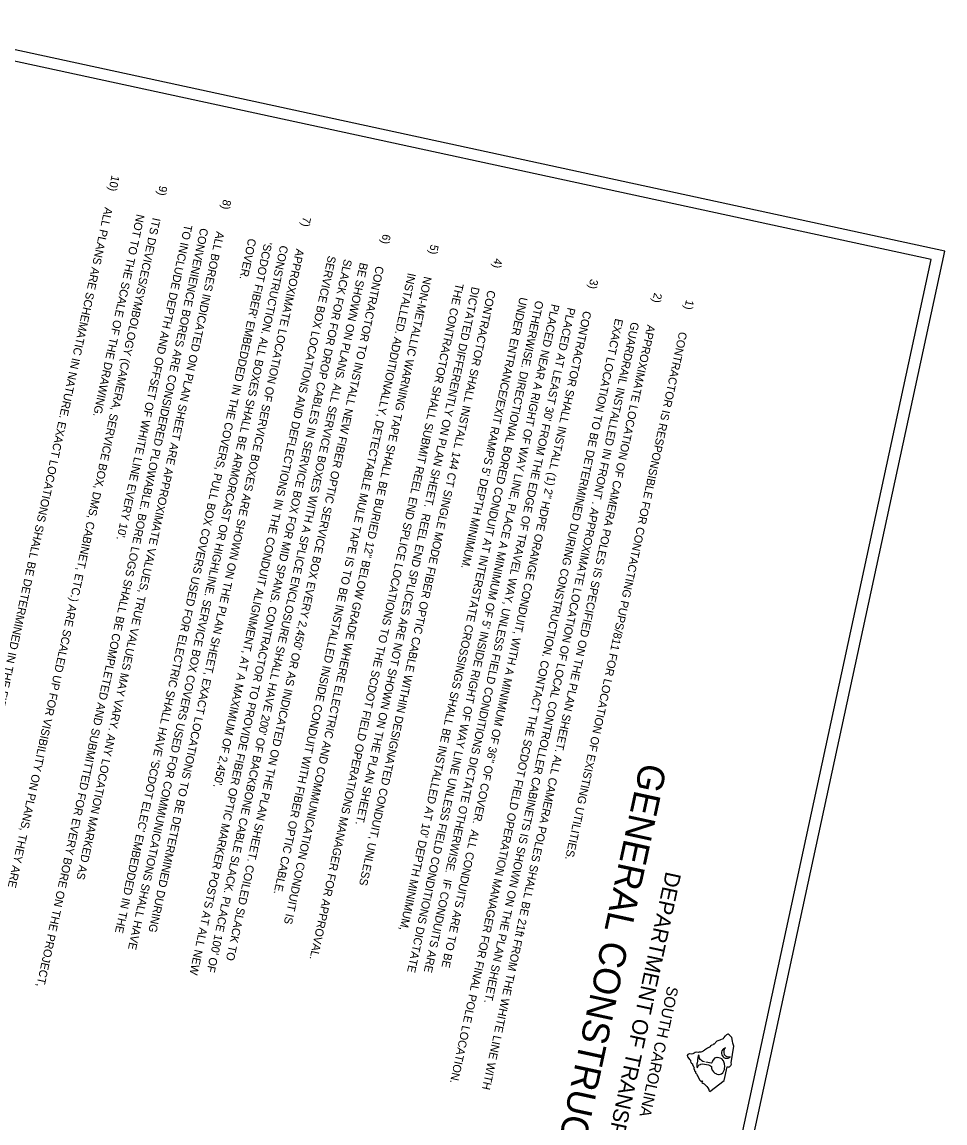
# Model space of a CAD drawing. Extents: x 1897817 to 2050613, y 442539 to 798440.
# Drawn here: x 1977576 to 1979013, y 783329 to 785042 of the extents above; entities that cross this region are included whole.
import ezdxf

# ---------------------------------------------------------------- set-up
doc = ezdxf.new("R2010")
doc.units = 0
for name, color, linetype in [('Default', 7, 'Continuous'), ('RD_SHT_Bndy', 7, 'Continuous'), ('RD_SHT_IplotShp', 7, 'Continuous')]:
    doc.layers.add(name, color=color, linetype=linetype)

msp = doc.modelspace()

# ---------------------------------------------------------------- linework, layer by layer
at = {"layer": 'Default'}
for p, q in [((1978668.6, 783462), (1978667.4, 783459.9)), ((1978671, 783445.8), (1978671, 783445.8)), ((1978633, 783426.7), (1978631.8, 783427.6)), ((1978634.1, 783425.9), (1978633, 783426.7)), ((1978635.6, 783424.9), (1978634.1, 783425.9)), ((1978638.3, 783424.2), (1978635.6, 783424.9)), ((1978649, 783421.9), (1978640.2, 783423.8)), ((1978647.7, 783418.1), (1978649.2, 783416.7)), ((1978669.5, 783413.7), (1978669.5, 783413.7)), ((1978646.5, 783378.1), (1978668.9, 783394.9))]:
    msp.add_line(p, q, dxfattribs=at)
for points in [[(1978667.4, 783459.9), (1978665.6, 783459.2), (1978663, 783458.6), (1978662.1, 783458), (1978657.6, 783456.3), (1978655.4, 783454), (1978654.7, 783453), (1978653.1, 783451.6), (1978652.4, 783451.5), (1978652, 783450.7), (1978649.9, 783450.2), (1978647.9, 783449.1), (1978646.9, 783447.5), (1978646.1, 783446.9), (1978642.8, 783445.4), (1978641.4, 783444.3), (1978638.3, 783442.4), (1978637.7, 783441.8), (1978636.4, 783441.4), (1978635.9, 783440.3), (1978632.8, 783439.2), (1978630.5, 783439.3), (1978629.8, 783439), (1978628.9, 783438.8), (1978625.5, 783439.1), (1978624, 783438.8), (1978622, 783437.4), (1978620.2, 783436.8), (1978617.6, 783436.3), (1978615.7, 783436.4), (1978614.9, 783436.8), (1978613.3, 783436.3), (1978612.6, 783435.8), (1978611.5, 783433.9), (1978611.9, 783432.1), (1978613.8, 783429.1), (1978615.1, 783427.8), (1978616.1, 783427.6), (1978616.7, 783426.8), (1978616.5, 783425), (1978617.3, 783423.2), (1978618.1, 783422.2), (1978619.4, 783420.9), (1978619.5, 783419.9), (1978620.5, 783417.4), (1978621.9, 783416.4), (1978622.1, 783415.5), (1978621.9, 783414.6), (1978621.8, 783413.6), (1978622.7, 783411.3), (1978622.8, 783410.3), (1978624.2, 783409.3), (1978624.5, 783408.2), (1978624.2, 783407.6), (1978624.3, 783406.8), (1978626.4, 783404.8), (1978626.9, 783402.7), (1978628.5, 783400.9), (1978628.9, 783399), (1978631.2, 783395.5), (1978632.7, 783394.2), (1978633.5, 783394.2), (1978634.3, 783394.5), (1978635, 783394), (1978634.4, 783392.2), (1978635.8, 783390.9), (1978637.6, 783390), (1978642.2, 783386), (1978643.7, 783383.9), (1978644.8, 783381.2)], [(1978673.4, 783416.3), (1978674.3, 783416.5), (1978675.2, 783416.1), (1978676, 783416.3), (1978677, 783416.4), (1978679.1, 783418.4), (1978680.1, 783420.7), (1978679.8, 783422.4), (1978684.1, 783448.4), (1978683.2, 783450.1), (1978682.5, 783453.1), (1978681.7, 783456.2), (1978681.1, 783461.8), (1978676.9, 783466.2), (1978675.3, 783467.2), (1978674.5, 783467.4), (1978672.4, 783466.2), (1978670.8, 783464.7), (1978669.9, 783464.2), (1978668.6, 783462)], [(1978631.8, 783427.6), (1978630.4, 783429.3), (1978629.8, 783432.9), (1978630, 783433.8), (1978629.1, 783434.3), (1978628.1, 783431.1), (1978627.7, 783430.2), (1978627.2, 783427.7), (1978627.3, 783425.8), (1978626.8, 783422.3), (1978626.5, 783421.5), (1978626.5, 783417), (1978626.8, 783415), (1978627.7, 783416.5), (1978628.4, 783418.1), (1978629.9, 783419.3)], [(1978650.2, 783423.6), (1978649.8, 783422.8), (1978649, 783422)], [(1978657.6, 783430.5), (1978656.8, 783430.7), (1978653.9, 783429.6), (1978651.8, 783426.8), (1978651, 783426.1), (1978651, 783425.2), (1978650.2, 783423.6)], [(1978665.9, 783428.1), (1978665.3, 783428.7), (1978662.8, 783430), (1978658.6, 783430.8), (1978657.6, 783430.5)], [(1978667.7, 783425.6), (1978667.5, 783426.4), (1978665.9, 783428.1)], [(1978669.5, 783413.7), (1978670, 783416.9), (1978669.6, 783421.1), (1978667.7, 783425.6)], [(1978629.9, 783419.3), (1978632, 783420.2)], [(1978632, 783420.2), (1978632.6, 783420.4), (1978635.9, 783420.8)], [(1978635.9, 783420.8), (1978638.5, 783420.6)], [(1978638.5, 783420.6), (1978644.4, 783419.3), (1978647.7, 783418.1)], [(1978649.2, 783416.7), (1978649.3, 783414.9), (1978649.4, 783414.4), (1978649.4, 783414.4), (1978650.3, 783411.2), (1978650.6, 783410.7), (1978652.1, 783408.4), (1978653.3, 783407.5), (1978654.3, 783406.7), (1978656.1, 783405.9), (1978657.1, 783405.5)], [(1978661, 783404.5), (1978663.3, 783404.8), (1978665, 783405.6), (1978666.6, 783406.9), (1978667.5, 783408.3), (1978667.8, 783409)], [(1978667.8, 783409), (1978669.2, 783412.3), (1978669.5, 783413.7)], [(1978668.9, 783394.9), (1978668.9, 783395), (1978673.4, 783416.3)], [(1978657.1, 783405.5), (1978657.7, 783405), (1978660.2, 783404.5), (1978661, 783404.5)], [(1978644.8, 783381.2), (1978645, 783380.1), (1978645.8, 783379), (1978646.5, 783378.1)]]:
    msp.add_lwpolyline(points, dxfattribs=at)
for centre, major_axis, start_param, end_param in [((1978672.9, 783437.9), (-7.97, 1.72), 5.80475, 6.314402), ((1978672.9, 783437.9), (-7.97, 1.72), 5.447207, 5.79938), ((1978676.1, 783439.7), (-7.82, 1.69), 5.62785, 8.38372), ((1978672.9, 783437.9), (-7.97, 1.72), 5.160801, 5.435937), ((1978672.9, 783437.9), (-7.97, 1.72), 0.031979, 0.55843), ((1978672.9, 783437.9), (-7.97, 1.72), 0.563702, 0.788107), ((1978672.9, 783437.9), (-7.97, 1.72), 0.803027, 1.195383), ((1978672.9, 783437.9), (-7.97, 1.72), 1.204989, 1.500149), ((1978672.9, 783437.9), (-7.97, 1.72), 1.504214, 1.84923), ((1978672.9, 783437.9), (-7.97, 1.72), 1.863481, 2.248857), ((1978672.9, 783437.9), (-7.97, 1.72), 2.259865, 2.562019)]:
    msp.add_ellipse(centre, major_axis=major_axis, ratio=0.999097, start_param=start_param, end_param=end_param, dxfattribs=at)
at = {"layer": 'RD_SHT_Bndy'}
for p, q in [((1978991.1, 784672.1), (1977385.5, 785019.6)), ((1978448.1, 782163.8), (1978991.1, 784672.1))]:
    msp.add_line(p, q, dxfattribs=at)
at = {"layer": 'RD_SHT_IplotShp'}
msp.add_lwpolyline([(1977366.1, 785041.7), (1976813.4, 782488), (1978459.8, 782131.6), (1979012.6, 784685.3)], close=True, dxfattribs=at)

# ---------------------------------------------------------------- texts
at = {"layer": 'Default'}
for s, height, p in [('10)', 12.71, (1977715.7, 784803.9)), ('9)  ', 12.71, (1977790.2, 784787.8)), ('8)', 12.71, (1977889.5, 784766.3)), ('ALL PLANS ARE SCHEMATIC IN NATURE. EXACT LOCATIONS SHALL BE DETERMINED IN THE FIELD.', 12.706, (1977704.9, 784754.3)), ('NOT TO THE SCALE OF THE DRAWING.', 12.706, (1977754.6, 784743.5)), ('ITS DEVICES/SYMBOLOGY (CAMERA, SERVICE BOX, DMS, CABINET, ETC.) ARE SCALED UP FOR VISIBILITY ON PLANS, THEY ARE', 12.7057, (1977779.4, 784738.1)), ('7)', 12.71, (1978013.7, 784739.4)), ('CONVENIENCE BORES ARE CONSIDERED PLOWABLE. BORE LOGS SHALL BE COMPLETED AND SUBMITTED FOR EVERY BORE ON THE PROJECT, ', 12.7057, (1977853.9, 784722)), ('ALL BORES INDICATED ON PLAN SHEET ARE APPROXIMATE VALUES, TRUE VALUES MAY VARY. ANY LOCATION MARKED AS', 12.7057, (1977878.8, 784716.6)), ("TO INCLUDE DEPTH AND OFFSET OF WHITE LINE EVERY 10'.", 12.706, (1977829.1, 784727.4)), ('6)', 12.71, (1978137.9, 784712.5)), ("'SCDOT FIBER' EMBEDDED IN THE COVERS, PULL BOX COVERS USED FOR ELECTRIC SHALL HAVE 'SCDOT ELEC' EMBEDDED IN THE ", 12.7057, (1977953.3, 784700.5)), ('CONSTRUCTION. ALL BOXES SHALL BE ARMORCAST OR HIGHLINE. SERVICE BOX COVERS USED FOR COMMUNICATIONS SHALL HAVE ', 12.7057, (1977978.1, 784695.1)), ('COVER.', 12.71, (1977928.4, 784705.9)), ('5)', 12.71, (1978212.4, 784696.4)), ('APPROXIMATE LOCATION OF SERVICE BOXES ARE SHOWN ON THE PLAN SHEET, EXACT LOCATIONS TO BE DETERMINED DURING ', 12.7057, (1978002.9, 784689.7)), ("SERVICE BOX LOCATIONS AND DEFLECTIONS IN THE CONDUIT ALIGNMENT, AT A MAXIMUM OF 2,450'. ", 12.706, (1978052.6, 784679)), ('4)', 12.71, (1978311.7, 784674.9)), ('SLACK FOR FOR DROP CABLES IN SERVICE BOX FOR MID SPANS. CONTRACTOR TO PROVIDE FIBER OPTIC MARKER POSTS AT ALL NEW ', 12.7057, (1978077.5, 784673.6)), ("BE SHOWN ON PLANS. ALL SERVICE BOXES WITH A SPLICE ENCLOSURE SHALL HAVE 200' OF BACKBONE CABLE SLACK. PLACE 100' OF ", 12.7057, (1978102.3, 784668.2)), ("CONTRACTOR TO INSTALL NEW FIBER OPTIC SERVICE BOX EVERY 2,450' OR AS INDICATED ON THE PLAN SHEET. COILED SLACK TO ", 12.7057, (1978127.1, 784662.9)), ('INSTALLED. ADDITIONALLY, DETECTABLE MULE TAPE IS TO BE INSTALLED INSIDE CONDUIT WITH FIBER OPTIC CABLE.', 12.7057, (1978176.8, 784652.1)), ('NON-METALLIC WARNING TAPE SHALL BE BURIED 12" BELOW GRADE WHERE ELECTRIC AND COMMUNICATION CONDUIT IS ', 12.7057, (1978201.6, 784646.7)), ('3)', 12.71, (1978460.7, 784642.6)), ('THE CONTRACTOR SHALL SUBMIT REEL END SPLICE LOCATIONS TO THE SCDOT FIELD OPERATIONS MANAGER FOR APPROVAL.', 12.7057, (1978251.3, 784636)), ('DICTATED DIFFERENTLY ON PLAN SHEET.  REEL END SPLICES ARE NOT SHOWN ON THE PLAN SHEET. ', 12.706, (1978276.1, 784630.6)), ('CONTRACTOR SHALL INSTALL 144 CT SINGLE MODE FIBER OPTIC CABLE WITHIN DESIGNATED CONDUIT, UNLESS ', 12.706, (1978301, 784625.2)), ("OTHERWISE. DIRECTIONAL BORED CONDUIT AT INTERSTATE CROSSINGS SHALL BE INSTALLED AT 10' DEPTH MINIMUM, ", 12.7057, (1978375.5, 784609.1)), ("UNDER ENTRANCE/EXIT RAMPS 5' DEPTH MINIMUM.", 12.706, (1978350.7, 784614.5)), ('2)', 12.71, (1978560.1, 784621.1)), ('1)', 12.71, (1978609.8, 784610.4)), ("PLACED NEAR A RIGHT OF WAY LINE, PLACE A MINIMUM OF 5' INSIDE RIGHT OF WAY LINE UNLESS FIELD CONDITIONS DICTATE", 12.7057, (1978400.3, 784603.7)), ("PLACED AT LEAST 30' FROM THE EDGE OF TRAVEL WAY, UNLESS FIELD CONDITIONS DICTATE OTHERWISE.  IF CONDUITS ARE", 12.7057, (1978425.2, 784598.3)), ('CONTRACTOR SHALL INSTALL (1) 2" HDPE ORANGE CONDUIT, WITH A MINIMUM OF 36" OF COVER.  ALL CONDUITS ARE TO BE ', 12.7057, (1978450, 784593)), ('           EXACT LOCATION TO BE DETERMINED DURING CONSTRUCTION. CONTACT THE SCDOT FIELD OPERATION MANAGER FOR FINAL POLE LOCATION.', 12.7057, (1978510.4, 784631.9)), ('APPROXIMATE LOCATION OF CAMERA POLES IS SPECIFIED ON THE PLAN SHEET. ALL CAMERA POLES SHALL BE 21ft FROM THE WHITE LINE WITH', 12.7057, (1978549.3, 784571.5)), ('           GUARDRAIL INSTALLED IN FRONT . APPROXIMATE LOCATION OF LOCAL CONTROLLER CABINETS IS SHOWN ON THE PLAN SHEET.', 12.7057, (1978535.3, 784626.5)), ('CONTRACTOR IS RESPONSIBLE FOR CONTACTING PUPS/811 FOR LOCATION OF EXISTING UTILITIES. ', 12.706, (1978599, 784560.7)), ('GENERAL CONSTRUCTION NOTE', 41.774, (1978539, 783890.8)), ('DEPARTMENT OF TRANSPORTATION', 24.361, (1978578.3, 783721.2)), ('SOUTH CAROLINA', 17.406, (1978580.8, 783542.8))]:
    msp.add_text(s, height=height, rotation=257.7861, dxfattribs=at).set_placement(p)

doc.saveas('drawing.dxf')
